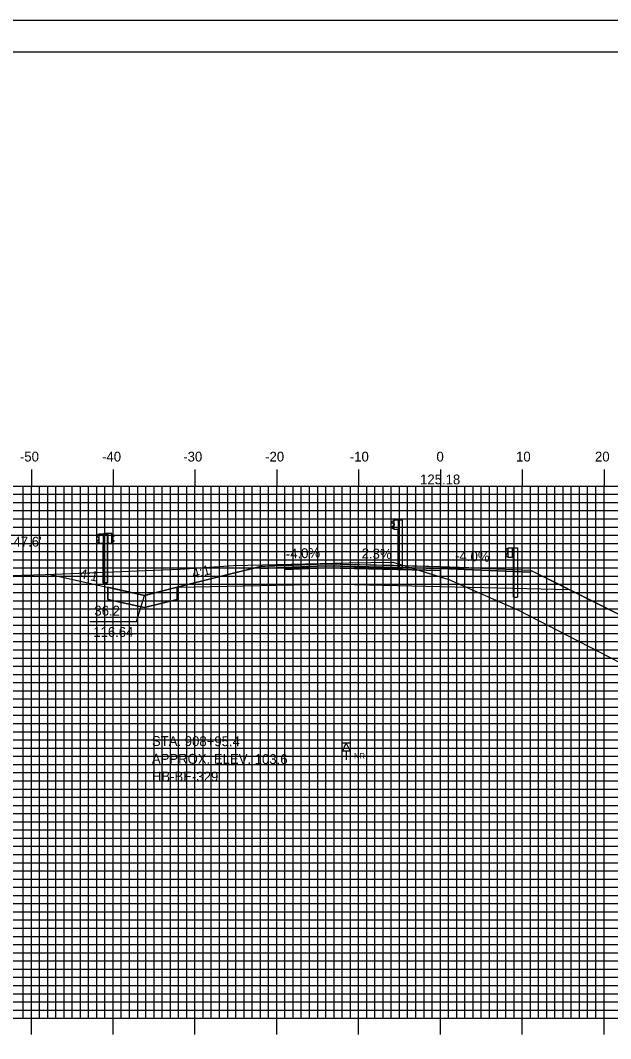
# Model space of a CAD drawing. Extents: x 858684 to 859027, y 364765 to 364985.
# Drawn here: x 858798.5 to 858870.7, y 364860.8 to 364985.2 of the extents above; entities that cross this region are included whole.
import ezdxf

# ---------------------------------------------------------------- set-up
doc = ezdxf.new("R2010")
doc.units = 0
for name, color, linetype in [('ANNOTATION', 7, 'Continuous'), ('BORDER', 7, 'Continuous'), ('BORING - NO REFUSAL', 7, 'Continuous'), ('D_Guardrail_Beam_Rt', 7, 'Continuous'), ('D_Roadway_Centerline', 7, 'Continuous'), ('D_Roadway_Centerline_Text', 7, 'Continuous'), ('D_Roadway_Edge_Shoulder', 7, 'Continuous'), ('D_Roadway_Edge_TW', 7, 'Continuous'), ('D_Roadway_FinishedGrade', 7, 'Continuous'), ('D_Roadway_Pavement', 7, 'Continuous'), ('D_Roadway_SlopeLines', 7, 'Continuous'), ('D_Roadway_SubGrade', 7, 'Continuous'), ('D_Text_Standard', 7, 'Continuous'), ('H_V ANNOTATION', 7, 'Continuous'), ('M_Guardrail', 7, 'Continuous'), ('M_Roadway_Centerline', 7, 'Continuous'), ('MAJOR', 7, 'Continuous'), ('MINOR', 7, 'Continuous'), ('PLOT BOUNDARY', 7, 'Continuous'), ('S_Roadway_Centerline', 7, 'Continuous')]:
    doc.layers.add(name, color=color, linetype=linetype)

msp = doc.modelspace()

# ---------------------------------------------------------------- linework, layer by layer
at = {"layer": 'ANNOTATION'}
msp.add_lwpolyline([(858807.02, 364911.76), (858812.72, 364911.76), (858813.69, 364914.95)], dxfattribs=at)
at = {"layer": 'BORDER'}
msp.add_lwpolyline([(858700.25, 364771.3), (859020.25, 364771.3), (859020.25, 364981.3), (858700.25, 364981.3)], close=True, dxfattribs=at)
at = {"layer": 'BORING - NO REFUSAL'}
for p, q in [((858838.83, 364896.9), (858837.87, 364896.9)), ((858838.35, 364895.94), (858838.35, 364894.88))]:
    msp.add_line(p, q, dxfattribs=at)
msp.add_lwpolyline([(858838.35, 364896.9), (858838.83, 364895.94), (858837.87, 364895.94)], close=True, dxfattribs=at)
at = {"layer": 'D_Guardrail_Beam_Rt'}
for p, q in [((858858.03, 364920.64), (858857.88, 364920.54)), ((858858.12, 364920.66), (858858.04, 364920.65)), ((858858.12, 364920.75), (858858.81, 364920.75)), ((858858.12, 364919.58), (858858.12, 364920.75)), ((858858.64, 364920.75), (858858.64, 364919.58)), ((858858.74, 364920.75), (858858.74, 364919.58)), ((858858.81, 364920.75), (858859.28, 364920.75)), ((858858.81, 364920.75), (858858.81, 364919.58)), ((858859.28, 364920.75), (858859.28, 364914.75)), ((858857.88, 364920.4), (858858.08, 364920.26)), ((858858.08, 364920.06), (858857.88, 364919.93)), ((858857.88, 364919.79), (858858.03, 364919.69)), ((858858.04, 364919.68), (858858.12, 364919.66)), ((858858.11, 364920.2), (858858.11, 364920.13)), ((858858.81, 364919.58), (858858.12, 364919.58)), ((858858.78, 364914.75), (858858.78, 364919.58)), ((858858.78, 364914.75), (858859.28, 364914.75))]:
    msp.add_line(p, q, dxfattribs=at)
for centre, major_axis, start_param, end_param in [((858858.05, 364920.61), (-0.0417, 0), 4.907132, 5.323254), ((858857.93, 364920.47), (-0.0877, 0), 5.323254, 7.243116), ((858857.93, 364919.86), (-0.0877, 0), 5.323254, 7.243116), ((858858.05, 364919.72), (-0.0417, 0), 0.959931, 1.376053), ((858858.03, 364920.2), (0.0789, 0), 0, 0.959931), ((858858.03, 364920.13), (0.0789, 0), 5.323254, 6.283185)]:
    msp.add_ellipse(centre, major_axis=major_axis, ratio=0.995501, start_param=start_param, end_param=end_param, dxfattribs=at)
at = {"layer": 'D_Roadway_Centerline'}
for points in [[(858817.67, 364915.94), (858817.67, 364915.94), (858820.77, 364916.72), (858827.85, 364918.49), (858827.85, 364918.49), (858828.43, 364918.51), (858830.85, 364918.61), (858830.85, 364918.61), (858835.84, 364918.81), (858835.85, 364918.81), (858835.86, 364918.81), (858844.12, 364918.62), (858849.85, 364918.48), (858849.86, 364918.48), (858854.5, 364918.3), (858857.85, 364918.16), (858857.85, 364918.16), (858858.88, 364918.12), (858860.85, 364918.04), (858865.14, 364915.9), (858865.69, 364915.62), (858865.7, 364915.62), (858937.52, 364879.71)], [(858802.21, 364917.5), (858813.69, 364914.95)]]:
    msp.add_lwpolyline(points, dxfattribs=at)
at = {"layer": 'D_Roadway_Edge_Shoulder'}
for points in [[(858835.85, 364918.81), (858830.85, 364918.61), (858830.85, 364918.61), (858827.85, 364918.49), (858827.85, 364918.24), (858830.85, 364918.36), (858835.85, 364918.56)], [(858849.85, 364918.48), (858857.85, 364918.16), (858857.85, 364918.16), (858860.85, 364918.04), (858860.85, 364917.79), (858849.85, 364918.23)]]:
    msp.add_lwpolyline(points, close=True, dxfattribs=at)
at = {"layer": 'D_Roadway_Edge_TW'}
msp.add_lwpolyline([(858835.85, 364918.81), (858849.85, 364918.48), (858849.85, 364918.23), (858835.85, 364918.56)], close=True, dxfattribs=at)
at = {"layer": 'D_Roadway_FinishedGrade'}
for p, q in [((858817.67, 364915.94), (858813.69, 364914.95)), ((858817.69, 364915.94), (858817.67, 364915.94))]:
    msp.add_line(p, q, dxfattribs=at)
msp.add_lwpolyline([(858817.69, 364915.95), (858817.69, 364914.45), (858813.69, 364913.45), (858809.2, 364914.45), (858809.2, 364915.95), (858813.69, 364914.95)], close=True, dxfattribs=at)
msp.add_lwpolyline([(858813.69, 364914.95), (858809.2, 364915.95), (858809.2, 364914.45), (858813.69, 364913.45), (858817.69, 364914.45), (858817.69, 364915.94)], dxfattribs=at)
at = {"layer": 'D_Roadway_Pavement'}
for points in [[(858835.85, 364918.56), (858830.85, 364918.36), (858830.85, 364918.11), (858835.85, 364918.31)], [(858835.85, 364918.56), (858849.85, 364918.23), (858849.85, 364917.98), (858835.85, 364918.31)]]:
    msp.add_lwpolyline(points, close=True, dxfattribs=at)
msp.add_lwpolyline([(858849.85, 364918.23), (858849.85, 364917.98)], dxfattribs=at)
msp.add_lwpolyline([(858849.85, 364918.23), (858849.85, 364917.98)], dxfattribs=at)
msp.add_lwpolyline([(858849.85, 364918.23), (858849.85, 364917.98)], dxfattribs=at)
at = {"layer": 'D_Roadway_SlopeLines'}
msp.add_line((858827.85, 364918.49), (858813.69, 364914.95), dxfattribs=at)
msp.add_lwpolyline([(858860.85, 364918.04), (858937.52, 364879.71)], dxfattribs=at)
at = {"layer": 'D_Roadway_SubGrade'}
for points in [[(858835.85, 364918.31), (858830.85, 364918.11), (858830.85, 364918.36), (858827.85, 364918.24), (858827.85, 364918.49), (858817.67, 364915.94), (858835.85, 364916.31)], [(858835.85, 364918.31), (858849.85, 364917.98), (858849.85, 364915.98), (858835.85, 364916.31)], [(858849.85, 364917.98), (858849.85, 364918.23), (858860.85, 364917.79), (858860.85, 364918.04), (858865.69, 364915.62), (858849.85, 364915.98)]]:
    msp.add_lwpolyline(points, close=True, dxfattribs=at)
at = {"layer": 'M_Guardrail'}
for p, q in [((858844.1, 364924.07), (858843.96, 364923.97)), ((858843.96, 364923.83), (858844.16, 364923.69)), ((858844.16, 364923.47), (858843.96, 364923.34)), ((858843.96, 364923.19), (858844.1, 364923.09)), ((858844.2, 364924.09), (858844.12, 364924.08)), ((858844.12, 364923.09), (858844.2, 364923.07)), ((858844.19, 364923.63), (858844.19, 364923.54)), ((858844.2, 364924.16), (858844.69, 364924.16)), ((858844.2, 364923), (858844.2, 364924.16)), ((858844.69, 364924.16), (858845.18, 364924.16)), ((858844.69, 364924.16), (858844.69, 364923)), ((858845.18, 364924.16), (858845.18, 364918.16)), ((858808.04, 364922.37), (858807.89, 364922.27)), ((858807.89, 364922.13), (858808.09, 364921.99)), ((858808.14, 364922.39), (858808.05, 364922.38)), ((858808.12, 364921.93), (858808.12, 364921.83)), ((858808.14, 364922.46), (858808.63, 364922.46)), ((858808.14, 364921.3), (858808.14, 364922.46)), ((858808.63, 364922.46), (858809.12, 364922.46)), ((858808.63, 364922.46), (858808.63, 364921.3)), ((858808.7, 364922.5), (858808.7, 364916.5)), ((858809.19, 364922.5), (858808.7, 364922.5)), ((858809.12, 364922.46), (858809.12, 364916.46)), ((858809.68, 364922.5), (858809.19, 364922.5)), ((858809.19, 364922.5), (858809.19, 364921.33)), ((858809.68, 364921.33), (858809.68, 364922.5)), ((858809.68, 364922.43), (858809.76, 364922.41)), ((858809.7, 364921.96), (858809.7, 364921.87)), ((858809.92, 364922.16), (858809.73, 364922.03)), ((858809.73, 364921.81), (858809.92, 364921.67)), ((858809.78, 364922.4), (858809.92, 364922.3)), ((858844.69, 364923), (858844.2, 364923)), ((858844.69, 364918.16), (858844.69, 364923)), ((858808.09, 364921.77), (858807.89, 364921.63)), ((858807.89, 364921.49), (858808.04, 364921.39)), ((858808.05, 364921.38), (858808.14, 364921.37)), ((858808.63, 364921.3), (858808.14, 364921.3)), ((858808.63, 364916.46), (858808.63, 364921.3)), ((858809.19, 364916.5), (858809.19, 364921.33)), ((858809.19, 364921.33), (858809.68, 364921.33)), ((858809.76, 364921.42), (858809.68, 364921.4)), ((858809.92, 364921.53), (858809.78, 364921.43)), ((858844.69, 364918.16), (858845.18, 364918.16)), ((858808.63, 364916.46), (858809.12, 364916.46)), ((858809.19, 364916.5), (858808.7, 364916.5))]:
    msp.add_line(p, q, dxfattribs=at)
for centre, major_axis, start_param, end_param in [((858844.01, 364923.9), (-0.0877, 0), 5.323254, 7.243116), ((858844.01, 364923.26), (-0.0877, 0), 5.323254, 7.243116), ((858844.13, 364924.04), (-0.0417, 0), 4.886922, 5.323254), ((858844.13, 364923.13), (-0.0417, 0), 0.959931, 1.396263), ((858844.11, 364923.63), (0.0789, 0), 0, 0.959931), ((858844.11, 364923.54), (0.0789, 0), 5.323254, 6.283185), ((858807.94, 364922.2), (-0.0877, 0), 5.323254, 7.243116), ((858808.06, 364922.34), (-0.0417, 0), 4.886922, 5.323254), ((858808.04, 364921.93), (0.0789, 0), 0, 0.959931), ((858808.04, 364921.83), (0.0789, 0), 5.323254, 6.283185), ((858809.77, 364921.96), (-0.0789, 0), 5.323254, 6.283185), ((858809.77, 364921.87), (-0.0789, 0), 6.283185, 7.243116), ((858809.76, 364922.37), (0.0417, 0), 0.959931, 1.396263), ((858809.87, 364922.23), (0.0877, 0), 5.323254, 7.243116), ((858807.94, 364921.56), (-0.0877, 0), 5.323254, 7.243116), ((858808.06, 364921.42), (-0.0417, 0), 0.959931, 1.396263), ((858809.76, 364921.46), (0.0417, 0), 4.886922, 5.323254), ((858809.87, 364921.6), (0.0877, 0), 5.323254, 7.243116)]:
    msp.add_ellipse(centre, major_axis=major_axis, ratio=0.995501, start_param=start_param, end_param=end_param, dxfattribs=at)
at = {"layer": 'MAJOR'}
for p, q in [((858799.85, 364930.31), (858799.85, 364928.3)), ((858809.85, 364930.31), (858809.85, 364928.3)), ((858819.85, 364930.31), (858819.85, 364928.3)), ((858829.85, 364930.31), (858829.85, 364928.3)), ((858839.85, 364930.31), (858839.85, 364928.3)), ((858849.85, 364930.31), (858849.85, 364928.3)), ((858859.85, 364930.31), (858859.85, 364928.3)), ((858869.85, 364930.31), (858869.85, 364928.3)), ((858709.85, 364928.3), (858989.85, 364928.3)), ((858709.85, 364928.3), (858989.85, 364928.3)), ((858799.85, 364863.3), (858799.85, 364928.3)), ((858809.85, 364863.3), (858809.85, 364928.3)), ((858819.85, 364863.3), (858819.85, 364928.3)), ((858829.85, 364863.3), (858829.85, 364928.3)), ((858839.85, 364863.3), (858839.85, 364928.3)), ((858849.85, 364863.3), (858849.85, 364928.3)), ((858859.85, 364863.3), (858859.85, 364928.3)), ((858869.85, 364863.3), (858869.85, 364928.3)), ((858709.85, 364923.3), (858989.85, 364923.3)), ((858709.85, 364918.3), (858989.85, 364918.3)), ((858709.85, 364913.3), (858989.85, 364913.3)), ((858709.85, 364908.3), (858989.85, 364908.3)), ((858709.85, 364903.3), (858989.85, 364903.3)), ((858709.85, 364898.3), (858989.85, 364898.3)), ((858709.85, 364893.3), (858989.85, 364893.3)), ((858709.85, 364888.3), (858989.85, 364888.3)), ((858709.85, 364883.3), (858989.85, 364883.3)), ((858709.85, 364878.3), (858989.85, 364878.3)), ((858709.85, 364873.3), (858989.85, 364873.3)), ((858709.85, 364868.3), (858989.85, 364868.3)), ((858709.85, 364863.3), (858989.85, 364863.3)), ((858709.85, 364863.3), (858989.85, 364863.3)), ((858799.85, 364861.3), (858799.85, 364863.3)), ((858809.85, 364861.3), (858809.85, 364863.3)), ((858819.85, 364861.3), (858819.85, 364863.3)), ((858829.85, 364861.3), (858829.85, 364863.3)), ((858839.85, 364861.3), (858839.85, 364863.3)), ((858849.85, 364861.3), (858849.85, 364863.3)), ((858859.85, 364861.3), (858859.85, 364863.3)), ((858869.85, 364861.3), (858869.85, 364863.3))]:
    msp.add_line(p, q, dxfattribs=at)
at = {"layer": 'MINOR'}
for p, q in [((858798.85, 364863.3), (858798.85, 364928.3)), ((858800.85, 364863.3), (858800.85, 364928.3)), ((858801.85, 364863.3), (858801.85, 364928.3)), ((858802.85, 364863.3), (858802.85, 364928.3)), ((858803.85, 364863.3), (858803.85, 364928.3)), ((858804.85, 364863.3), (858804.85, 364928.3)), ((858805.85, 364863.3), (858805.85, 364928.3)), ((858806.85, 364863.3), (858806.85, 364928.3)), ((858807.85, 364863.3), (858807.85, 364928.3)), ((858808.85, 364863.3), (858808.85, 364928.3)), ((858810.85, 364863.3), (858810.85, 364928.3)), ((858811.85, 364863.3), (858811.85, 364928.3)), ((858812.85, 364863.3), (858812.85, 364928.3)), ((858813.85, 364863.3), (858813.85, 364928.3)), ((858814.85, 364863.3), (858814.85, 364928.3)), ((858815.85, 364863.3), (858815.85, 364928.3)), ((858816.85, 364863.3), (858816.85, 364928.3)), ((858817.85, 364863.3), (858817.85, 364928.3)), ((858818.85, 364863.3), (858818.85, 364928.3)), ((858820.85, 364863.3), (858820.85, 364928.3)), ((858821.85, 364863.3), (858821.85, 364928.3)), ((858822.85, 364863.3), (858822.85, 364928.3)), ((858823.85, 364863.3), (858823.85, 364928.3)), ((858824.85, 364863.3), (858824.85, 364928.3)), ((858825.85, 364863.3), (858825.85, 364928.3)), ((858826.85, 364863.3), (858826.85, 364928.3)), ((858827.85, 364863.3), (858827.85, 364928.3)), ((858828.85, 364863.3), (858828.85, 364928.3)), ((858830.85, 364863.3), (858830.85, 364928.3)), ((858831.85, 364863.3), (858831.85, 364928.3)), ((858832.85, 364863.3), (858832.85, 364928.3)), ((858833.85, 364863.3), (858833.85, 364928.3)), ((858834.85, 364863.3), (858834.85, 364928.3)), ((858835.85, 364863.3), (858835.85, 364928.3)), ((858836.85, 364863.3), (858836.85, 364928.3)), ((858837.85, 364863.3), (858837.85, 364928.3)), ((858838.85, 364863.3), (858838.85, 364928.3)), ((858840.85, 364863.3), (858840.85, 364928.3)), ((858841.85, 364863.3), (858841.85, 364928.3)), ((858842.85, 364863.3), (858842.85, 364928.3)), ((858843.85, 364863.3), (858843.85, 364928.3)), ((858844.85, 364863.3), (858844.85, 364928.3)), ((858845.85, 364863.3), (858845.85, 364928.3)), ((858846.85, 364863.3), (858846.85, 364928.3)), ((858847.85, 364863.3), (858847.85, 364928.3)), ((858848.85, 364863.3), (858848.85, 364928.3)), ((858850.85, 364863.3), (858850.85, 364928.3)), ((858851.85, 364863.3), (858851.85, 364928.3)), ((858852.85, 364863.3), (858852.85, 364928.3)), ((858853.85, 364863.3), (858853.85, 364928.3)), ((858854.85, 364863.3), (858854.85, 364928.3)), ((858855.85, 364863.3), (858855.85, 364928.3)), ((858856.85, 364863.3), (858856.85, 364928.3)), ((858857.85, 364863.3), (858857.85, 364928.3)), ((858858.85, 364863.3), (858858.85, 364928.3)), ((858860.85, 364863.3), (858860.85, 364928.3)), ((858861.85, 364863.3), (858861.85, 364928.3)), ((858862.85, 364863.3), (858862.85, 364928.3)), ((858863.85, 364863.3), (858863.85, 364928.3)), ((858864.85, 364863.3), (858864.85, 364928.3)), ((858865.85, 364863.3), (858865.85, 364928.3)), ((858866.85, 364863.3), (858866.85, 364928.3)), ((858867.85, 364863.3), (858867.85, 364928.3)), ((858868.85, 364863.3), (858868.85, 364928.3)), ((858709.85, 364927.3), (858989.85, 364927.3)), ((858709.85, 364926.3), (858989.85, 364926.3)), ((858709.85, 364925.3), (858989.85, 364925.3)), ((858709.85, 364924.3), (858989.85, 364924.3)), ((858709.85, 364922.3), (858989.85, 364922.3)), ((858709.85, 364921.3), (858989.85, 364921.3)), ((858709.85, 364920.3), (858989.85, 364920.3)), ((858709.85, 364919.3), (858989.85, 364919.3)), ((858709.85, 364917.3), (858989.85, 364917.3)), ((858709.85, 364916.3), (858989.85, 364916.3)), ((858709.85, 364915.3), (858989.85, 364915.3)), ((858709.85, 364914.3), (858989.85, 364914.3)), ((858709.85, 364912.3), (858989.85, 364912.3)), ((858709.85, 364911.3), (858989.85, 364911.3)), ((858709.85, 364910.3), (858989.85, 364910.3)), ((858709.85, 364909.3), (858989.85, 364909.3)), ((858709.85, 364907.3), (858989.85, 364907.3)), ((858709.85, 364906.3), (858989.85, 364906.3)), ((858709.85, 364905.3), (858989.85, 364905.3)), ((858709.85, 364904.3), (858989.85, 364904.3)), ((858709.85, 364902.3), (858989.85, 364902.3)), ((858709.85, 364901.3), (858989.85, 364901.3)), ((858709.85, 364900.3), (858989.85, 364900.3)), ((858709.85, 364899.3), (858989.85, 364899.3)), ((858709.85, 364897.3), (858989.85, 364897.3)), ((858709.85, 364896.3), (858989.85, 364896.3)), ((858709.85, 364895.3), (858989.85, 364895.3)), ((858709.85, 364894.3), (858989.85, 364894.3)), ((858709.85, 364892.3), (858989.85, 364892.3)), ((858709.85, 364891.3), (858989.85, 364891.3)), ((858709.85, 364890.3), (858989.85, 364890.3)), ((858709.85, 364889.3), (858989.85, 364889.3)), ((858709.85, 364887.3), (858989.85, 364887.3)), ((858709.85, 364886.3), (858989.85, 364886.3)), ((858709.85, 364885.3), (858989.85, 364885.3)), ((858709.85, 364884.3), (858989.85, 364884.3)), ((858709.85, 364882.3), (858989.85, 364882.3)), ((858709.85, 364881.3), (858989.85, 364881.3)), ((858709.85, 364880.3), (858989.85, 364880.3)), ((858709.85, 364879.3), (858989.85, 364879.3)), ((858709.85, 364877.3), (858989.85, 364877.3)), ((858709.85, 364876.3), (858989.85, 364876.3)), ((858709.85, 364875.3), (858989.85, 364875.3)), ((858709.85, 364874.3), (858989.85, 364874.3)), ((858709.85, 364872.3), (858989.85, 364872.3)), ((858709.85, 364871.3), (858989.85, 364871.3)), ((858709.85, 364870.3), (858989.85, 364870.3)), ((858709.85, 364869.3), (858989.85, 364869.3)), ((858709.85, 364867.3), (858989.85, 364867.3)), ((858709.85, 364866.3), (858989.85, 364866.3)), ((858709.85, 364865.3), (858989.85, 364865.3)), ((858709.85, 364864.3), (858989.85, 364864.3))]:
    msp.add_line(p, q, dxfattribs=at)
at = {"layer": 'PLOT BOUNDARY'}
msp.add_lwpolyline([(858684.06, 364765.18), (859024.06, 364765.18), (859024.06, 364985.18), (858684.06, 364985.18)], close=True, dxfattribs=at)
at = {"layer": 'S_Roadway_Centerline'}
msp.add_lwpolyline([(858791.46, 364917.22), (858801.59, 364917.48), (858818, 364918.14), (858824.58, 364918.58), (858838.64, 364918.92), (858844.05, 364919.02), (858850.88, 364916.87), (858859.4, 364913.15), (858875.43, 364904.86), (858879.29, 364902.99), (858899.1, 364893.63), (858900.38, 364893.08), (858910.71, 364888.45), (858915.53, 364886.48), (858923.68, 364882.65), (858954.04, 364876.19), (858960.9, 364873.39), (858962.43, 364872.98), (858971.15, 364871.85), (858973.79, 364871.77), (858976.66, 364871.57), (858989.85, 364870.79)], dxfattribs=at)

# ---------------------------------------------------------------- texts
at = {"layer": 'ANNOTATION'}
for s, rotation, p in [('-4.0%', 2.2905, (858830.98, 364919.41)), ('2.3%', 358.6864, (858840.22, 364919.49)), ('-4.0%', 357.7095, (858851.64, 364919.21)), ('4:1', 348.6438, (858805.68, 364917.06)), ('4:1', 14.0362, (858819.66, 364916.99))]:
    msp.add_text(s, height=1.2, rotation=rotation, dxfattribs=at).set_placement(p)
for s, p in [("36.2' ", (858807.56, 364912.48)), ('116.64', (858807.42, 364909.88))]:
    msp.add_text(s, height=1.2, dxfattribs=at).set_placement(p)
at = {"layer": 'BORING - NO REFUSAL'}
for s, p in [('STA. 908+95.4', (858814.59, 364896.56)), ('APPROX. ELEV. 103.6', (858814.58, 364894.4)), ('HB-BE-329', (858814.58, 364892.24))]:
    msp.add_text(s, height=1.2, rotation=359.8142, dxfattribs=at).set_placement(p)
msp.add_text('NR', height=0.7, dxfattribs=at).set_placement((858839.28, 364894.99))
at = {"layer": 'D_Roadway_Centerline_Text'}
msp.add_text('125.18', height=1.2, dxfattribs=at).set_placement((858847.37, 364928.51))
at = {"layer": 'D_Text_Standard'}
msp.add_text("47.6'", height=1.2, dxfattribs=at).set_placement((858797.67, 364920.91))
at = {"layer": 'H_V ANNOTATION'}
for s, p in [('-50', (858798.46, 364931.3)), ('-40', (858808.5, 364931.3)), ('-30', (858818.42, 364931.3)), ('-20', (858828.43, 364931.3)), ('-10', (858838.78, 364931.3)), ('0', (858849.37, 364931.3)), ('10', (858859.1, 364931.3)), ('20', (858868.75, 364931.3))]:
    msp.add_text(s, height=1.2, dxfattribs=at).set_placement(p)
at = {"layer": 'M_Roadway_Centerline'}
for s, p in [('C', (858824.57, 364918.58)), ('L', (858824.58, 364918.57))]:
    msp.add_text(s, height=0.0146, dxfattribs=at).set_placement(p)

doc.saveas('drawing.dxf')
